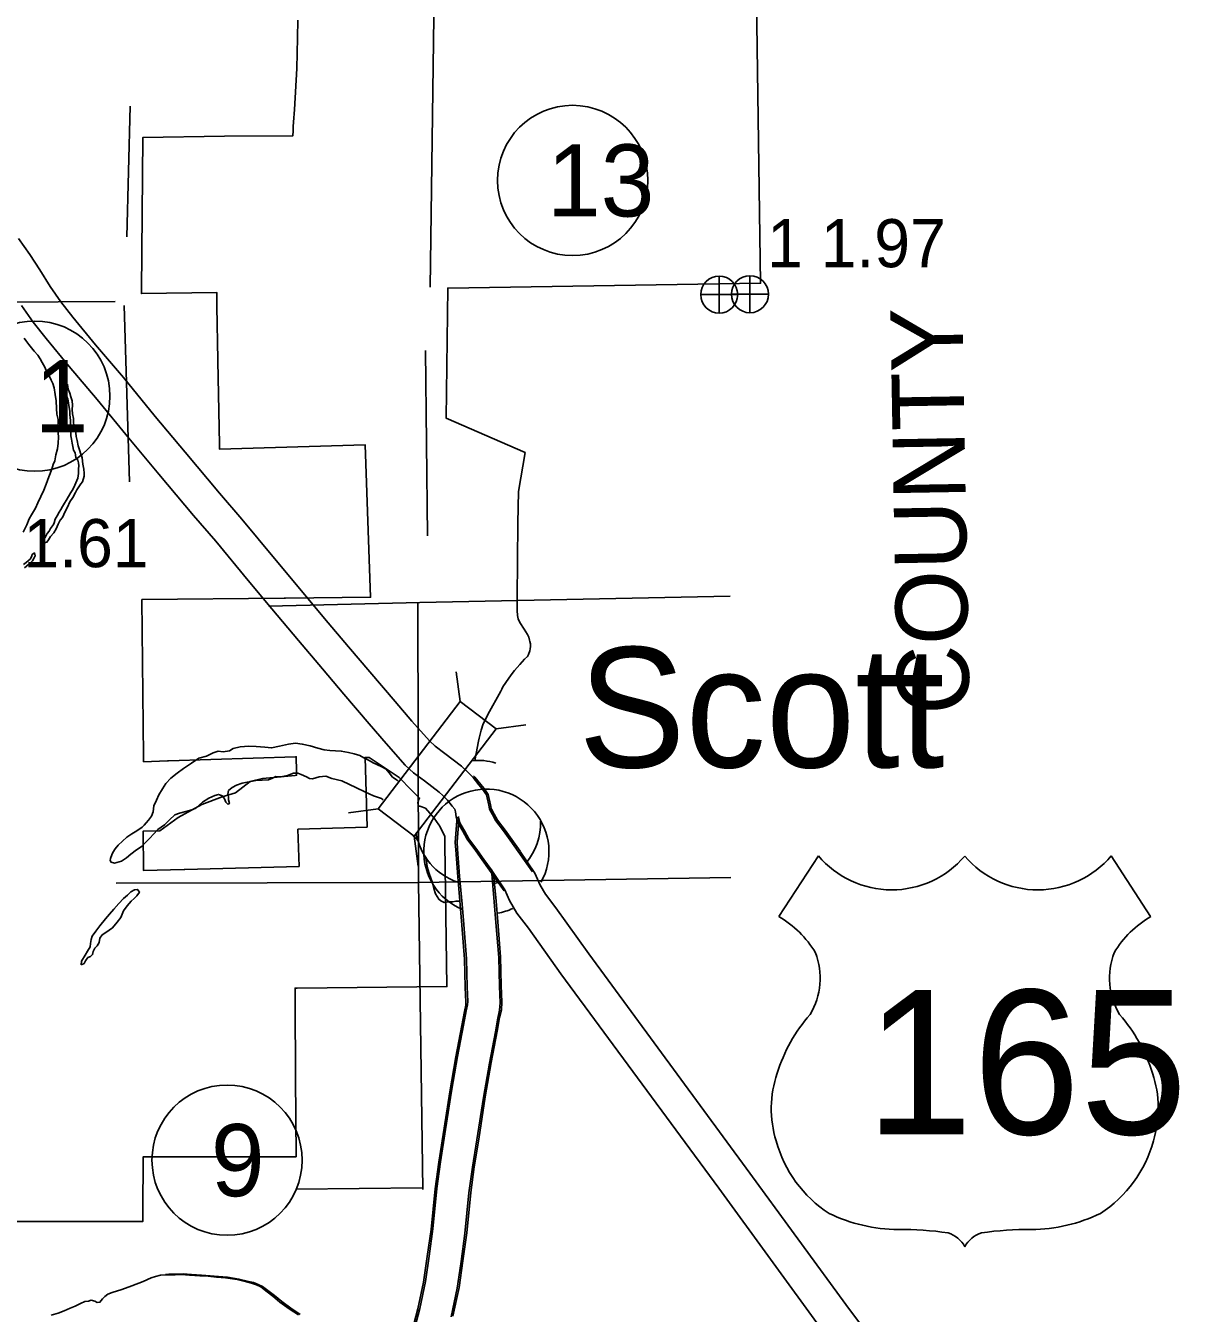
# Model space of a CAD drawing. Extents: x 1127717 to 1741049, y 2026793 to 2244711.
# Drawn here: x 1244517 to 1249585, y 2127719 to 2133375 of the extents above; entities that cross this region are included whole.
import ezdxf

# ---------------------------------------------------------------- set-up
doc = ezdxf.new("R2010")
doc.units = 0
for name, color, linetype in [('10', 7, 'Continuous'), ('15', 7, 'Continuous'), ('2', 7, 'Continuous'), ('20', 7, 'Continuous'), ('22', 7, 'Continuous'), ('24', 7, 'Continuous'), ('25', 7, 'Continuous'), ('26', 7, 'Continuous'), ('27', 7, 'Continuous'), ('30', 7, 'Continuous'), ('4', 7, 'Continuous'), ('5', 7, 'Continuous'), ('58', 7, 'Continuous'), ('6', 7, 'Continuous'), ('9', 7, 'Continuous')]:
    doc.layers.add(name, color=color, linetype=linetype)

msp = doc.modelspace()

# ---------------------------------------------------------------- linework, layer by layer
at = {"layer": '10'}
for points in [[(1246410.8, 2129898.7), (1246411.3, 2129882.2), (1246403.9, 2129787.4), (1246406, 2129754.8), (1246414.5, 2129636.5), (1246425.5, 2129513.7), (1246433.1, 2129423.7), (1246444.8, 2129274), (1246447.9, 2129150.7), (1246450.7, 2129085.6), (1246449.6, 2129072), (1246443.8, 2129045), (1246432.5, 2128982.8), (1246406, 2128845), (1246379.2, 2128691.6), (1246350.5, 2128504.5), (1246331, 2128382.1), (1246315.1, 2128264.8), (1246297.2, 2128087), (1246281, 2127967.5), (1246264.7, 2127856.1), (1246239.7, 2127738.1), (1246212.2, 2127631.6)], [(1246418.6, 2129901), (1246419.1, 2129884.5), (1246411.7, 2129789.7), (1246413.9, 2129757.1), (1246422.3, 2129638.8), (1246433.4, 2129515.9), (1246441, 2129426), (1246452.7, 2129276.3), (1246455.7, 2129153), (1246458.6, 2129087.9), (1246457.5, 2129074.3), (1246451.7, 2129047.3), (1246440.4, 2128985.1), (1246413.8, 2128847.3), (1246387, 2128693.9), (1246358.4, 2128506.7), (1246338.9, 2128384.4), (1246322.9, 2128267.1), (1246305.1, 2128089.3), (1246288.9, 2127969.8), (1246272.6, 2127858.4), (1246247.5, 2127740.4), (1246220, 2127633.9)], [(1246563.5, 2129654.9), (1246564, 2129648.6), (1246575, 2129526.7), (1246582.6, 2129435.8), (1246594.7, 2129281.7), (1246597.8, 2129155.8), (1246601, 2129082.9), (1246598.4, 2129050.3), (1246591, 2129015.8), (1246579.9, 2128955.2), (1246553.5, 2128817.9), (1246527.2, 2128667.4), (1246498.7, 2128481.3), (1246479.4, 2128360.2), (1246464.1, 2128247.2), (1246446.2, 2128069.4), (1246429.5, 2127946.6), (1246412.5, 2127829.6), (1246385.7, 2127703.7)], [(1246572.1, 2129648.3), (1246582.8, 2129529), (1246590.5, 2129438.1), (1246602.5, 2129284), (1246605.7, 2129158.1), (1246608.8, 2129085.2), (1246606.2, 2129052.5), (1246598.8, 2129018.1), (1246587.8, 2128957.4), (1246561.4, 2128820.2), (1246535.1, 2128669.7), (1246506.6, 2128483.6), (1246487.2, 2128362.4), (1246471.9, 2128249.5), (1246454.1, 2128071.7), (1246437.4, 2127948.8), (1246420.3, 2127831.9), (1246393.6, 2127706)]]:
    msp.add_lwpolyline(points, dxfattribs=at)
at = {"layer": '15'}
for points in [[(1244485, 2132440.8), (1244534.8, 2132370), (1244579.1, 2132302.4), (1244623.5, 2132228.8), (1244670.3, 2132162.7), (1244723.6, 2132094.4), (1244823, 2131973.7), (1244945.6, 2131829), (1245085.4, 2131658.1), (1245217, 2131501.5), (1245368.1, 2131321), (1245465.9, 2131207.5), (1245609.5, 2131034), (1245713.3, 2130910), (1245830, 2130770.8), (1245935.3, 2130646.3), (1246028.8, 2130535.9), (1246139.4, 2130405.9), (1246212.7, 2130319.6), (1246290, 2130232.8), (1246315.3, 2130209.6), (1246358.5, 2130178.4), (1246431.7, 2130122.5), (1246455.2, 2130099.7), (1246482, 2130072.1), (1246507.8, 2130040.2), (1246522.8, 2130021.1), (1246540.6, 2129995.9), (1246551.4, 2129950.4), (1246554, 2129934.3), (1246555, 2129930.9), (1246567.5, 2129909.5), (1246582.2, 2129882.4), (1246615.3, 2129838.5), (1246644.6, 2129797.3), (1246742.7, 2129657.8)], [(1244497.9, 2132146.5), (1244550, 2132073.2), (1244606.6, 2132000.5), (1244707.9, 2131877.6), (1244830.3, 2131733), (1244969.9, 2131562.4), (1245102, 2131405.1), (1245253.8, 2131223.9), (1245351.3, 2131110.7), (1245494.2, 2130938), (1245598.3, 2130813.6), (1245715.3, 2130674.2), (1245820.8, 2130549.4), (1245914.4, 2130438.8), (1246025.1, 2130308.8), (1246099.5, 2130221.1), (1246183.1, 2130127.3), (1246220.4, 2130093.2), (1246269, 2130058), (1246333.6, 2130008.7), (1246349.1, 2129993.6), (1246369.7, 2129972.5), (1246390.5, 2129946.7), (1246401.4, 2129932.9), (1246404.2, 2129920.9), (1246407.6, 2129900.2), (1246416.5, 2129870.7), (1246436.7, 2129836), (1246455.7, 2129801), (1246494.2, 2129749.9), (1246522.1, 2129710.6), (1246618, 2129574.3)], [(1246484.4, 2130080), (1246489.9, 2130074.4), (1246515.7, 2130042.4), (1246530.6, 2130023.4), (1246548.4, 2129998.2), (1246559.2, 2129952.7), (1246561.9, 2129936.5), (1246562.9, 2129933.2), (1246575.3, 2129911.8), (1246590, 2129884.7), (1246623.1, 2129840.8), (1246652.4, 2129799.5), (1246688.5, 2129748.4)], [(1246417.5, 2129895.8), (1246424.4, 2129873), (1246444.5, 2129838.3), (1246463.5, 2129803.3), (1246502.1, 2129752.2), (1246530, 2129712.9), (1246565.8, 2129662)], [(1246689.3, 2129747.1), (1246753.4, 2129652.1), (1246776.3, 2129600), (1246799.5, 2129560), (1246845.9, 2129500.5), (1246989.9, 2129297.3), (1247682.5, 2128356.4), (1248136.2, 2127734.8), (1248263.6, 2127566.8)], [(1246565, 2129663.2), (1246621.5, 2129579.4), (1246642.3, 2129532.1), (1246674.8, 2129475.9), (1246725.5, 2129410.9), (1246868.3, 2129209.5), (1247561.5, 2128267.7), (1248015.8, 2127645.2)]]:
    msp.add_lwpolyline(points, dxfattribs=at)
at = {"layer": '2'}
msp.add_lwpolyline([(1247726, 2133591.9), (1247745.1, 2132243.6), (1246370.9, 2132222.7), (1246363.4, 2131651.2), (1246710.2, 2131499.8), (1246682.1, 2131328.2), (1246678, 2131189.4), (1246676.3, 2130861.7), (1246675.2, 2130805.6), (1246676.9, 2130784.8), (1246679.7, 2130769.7), (1246687.2, 2130752.7), (1246706.9, 2130723.7), (1246720.7, 2130700.3), (1246726.9, 2130688.5), (1246730.4, 2130675.9), (1246731.7, 2130669.2), (1246733.6, 2130660.3), (1246734.1, 2130647.5), (1246733.5, 2130638.2), (1246731.4, 2130628.6), (1246725.4, 2130612.1), (1246720.5, 2130604.1), (1246708.3, 2130591.6), (1246688, 2130568.9), (1246663.6, 2130542.4), (1246649, 2130523.5), (1246626.4, 2130490.2), (1246613, 2130470.1), (1246607.9, 2130461.1), (1246603.3, 2130451.2), (1246546.9, 2130348.9), (1246525.2, 2130303.2), (1246519.2, 2130285.4), (1246516.9, 2130279.8), (1246509.1, 2130245.6), (1246506.4, 2130232.7), (1246495, 2130177.9), (1246489.6, 2130147.3)], dxfattribs=at)
at = {"layer": '20'}
for p, q in [((1246425.6, 2130406.4), (1246408, 2130537.3)), ((1246583, 2130286.3), (1246713.8, 2130303.9)), ((1246065.3, 2129934.2), (1245934.4, 2129916.6)), ((1246222.7, 2129814.1), (1246240.3, 2129683.3))]:
    msp.add_line(p, q, dxfattribs=at)
msp.add_lwpolyline([(1246222.7, 2129814.1), (1246583, 2130286.3), (1246425.6, 2130406.4), (1246065.3, 2129934.2)], close=True, dxfattribs=at)
at = {"layer": '22'}
for p, q in [((1247998.9, 2129728.8), (1247825.8, 2129461.1)), ((1249285.8, 2129728.8), (1249458.9, 2129461.1))]:
    msp.add_line(p, q, dxfattribs=at)
for centre, radius, start, end in [((1248321.2, 2129999.9), 421.2, 220.075, 319.6701), ((1248963.5, 2129999.9), 421.2, 220.3299, 319.925), ((1247599.7, 2129072.5), 449.7, 30.7809, 59.9883), ((1249685, 2129072.5), 449.7, 120.0117, 149.2191), ((1247698.6, 2129191.1), 308.3, 328.8105, 21.2108), ((1249586.1, 2129191.1), 308.3, 158.7892, 211.1895), ((1248504.7, 2128559.2), 719.2, 138.9565, 162.6913), ((1248780, 2128559.2), 719.2, 17.3087, 41.0435), ((1248267.3, 2128618.1), 475.2, 160.9576, 197.3819), ((1249017.4, 2128618.1), 475.2, 342.6181, 19.0424), ((1248344.7, 2128619.5), 549.9, 195.1074, 237.1312), ((1248940, 2128619.5), 549.9, 302.8688, 344.8926), ((1248354.9, 2128792.7), 706, 244.0771, 269.5779), ((1248929.8, 2128792.7), 706, 270.4221, 295.9229), ((1248371.2, 2126793.5), 1293.3, 81.1942, 90.9539), ((1248533, 2127953.1), 123.9, 28.0342, 72.9864), ((1248751.7, 2127953.1), 123.9, 107.0136, 151.9658), ((1248913.5, 2126793.5), 1293.3, 89.0461, 98.8058)]:
    msp.add_arc(centre, radius, start, end, dxfattribs=at)
at = {"layer": '24'}
for centre, start, end in [((1246503.4, 2129872.6), 73.3807, 95.8922), ((1246540.4, 2129746.6), 330.733, 246.9867), ((1246503.4, 2129872.6), 320.3322, 1.7396), ((1246503.4, 2129872.6), 189.0982, 251.1797), ((1246503.4, 2129872.6), 283.7891, 288.6769), ((1246540.4, 2129746.6), 280.4786, 294.8874)]:
    msp.add_arc(centre, 275, start, end, dxfattribs=at)
at = {"layer": '26'}
for p, q in [((1247563.4, 2132112.3), (1247563.4, 2132274.8)), ((1247698.6, 2132114.1), (1247698.6, 2132276.6)), ((1247482.2, 2132193.6), (1247644.7, 2132193.6)), ((1247617.4, 2132195.4), (1247779.9, 2132195.4))]:
    msp.add_line(p, q, dxfattribs=at)
for centre in [(1247563.4, 2132193.6), (1247698.6, 2132195.4)]:
    msp.add_circle(centre, 81.2, dxfattribs=at)
at = {"layer": '27'}
for centre in [(1246919.4, 2132695.3), (1244556.5, 2131747.8), (1245401.2, 2128391.4)]:
    msp.add_circle(centre, 330, dxfattribs=at)
at = {"layer": '4'}
msp.add_lwpolyline([(1245584.9, 2130825.6), (1246248.7, 2130840.5), (1247611, 2130868.6)], dxfattribs=at)
at = {"layer": '5'}
for points in [[(1246292.8, 2132227), (1246310.7, 2133522), (1246312.6, 2134233)], [(1244975.9, 2133020.9), (1244960.3, 2132447.8)], [(1243905.8, 2132158), (1244909.7, 2132163)], [(1244949.2, 2132146.2), (1244972, 2131371.1)], [(1246281.2, 2131134.6), (1246273.2, 2131948.2)], [(1246240, 2130840.3), (1246242.1, 2129613.8), (1246261.1, 2128262.7)], [(1244913.3, 2129607.7), (1246241.2, 2129611.8), (1247614, 2129633.3)], [(1245705.4, 2128263.4), (1246259.1, 2128270.2)]]:
    msp.add_lwpolyline(points, dxfattribs=at)
at = {"layer": '6'}
for points in [[(1245712.3, 2133398.7), (1245710.6, 2133323.5), (1245710.5, 2133322.4), (1245710.5, 2133321.4), (1245707.4, 2133186.9), (1245707.9, 2133186.9), (1245696.8, 2133007.4), (1245693.3, 2132952), (1245692.1, 2132932.3), (1245690.9, 2132913), (1245689.6, 2132891.1), (1245389.6, 2132890), (1245031.3, 2132884.5), (1245025, 2132212.5), (1245024.8, 2132198.3), (1245355.6, 2132203.4), (1245356.1, 2132181.1), (1245356.8, 2132141.9), (1245361.1, 2131907.3), (1245361.1, 2131904.6), (1245361.2, 2131902.4), (1245367.9, 2131535.7), (1245368.3, 2131514.5), (1246008.2, 2131533.6), (1246031.7, 2130864.2), (1245658.1, 2130860.4), (1245654.9, 2130860.4), (1245651.8, 2130860.4), (1245027, 2130854), (1245034.1, 2130166.3), (1245034.1, 2130164.6), (1245034.1, 2130163), (1245034.3, 2130141.9), (1245139.7, 2130145.3), (1245142, 2130145.4), (1245144.3, 2130145.5), (1245702.3, 2130163.7), (1245705, 2130163.8), (1245706.1, 2130100.4), (1245706.4, 2130082), (1245700.5, 2130081.4), (1245557.4, 2130067.7), (1245503, 2130054.3), (1245437.9, 2130005.3), (1245379.7, 2129987.9), (1245290.7, 2129953.9), (1245186.7, 2129896), (1245106.2, 2129838.7), (1245033.1, 2129837.3), (1245034.2, 2129663.8), (1245212.9, 2129668.5), (1245214.3, 2129668.6), (1245215.8, 2129668.6), (1245717.6, 2129681.8), (1245712.6, 2129845.4), (1246016.5, 2129854.5), (1246007.4, 2130160.3), (1246025, 2130159.9), (1246086.4, 2130118.8), (1246130.5, 2130089.4), (1246156.6, 2130071.9), (1246211.7, 2130017), (1246247.1, 2129981.7), (1246243.7, 2129976.7), (1246239.1, 2129961.7), (1246241.9, 2129947), (1246248.6, 2129946.8), (1246272.5, 2129937.6), (1246311.7, 2129894.5), (1246331.8, 2129863.9), (1246335.4, 2129858.4), (1246357.7, 2129812.8), (1246357.4, 2129779.9), (1246367, 2129154.1), (1245708.7, 2129147.4), (1245705.9, 2129147.4), (1245703.5, 2129147.4), (1245702.6, 2129147.4), (1245699.7, 2129147.3), (1245699.7, 2129141.8), (1245699.8, 2129136.7), (1245699.8, 2129124.2)], [(1245699.8, 2129124.2), (1245700.9, 2128968.7), (1245701.6, 2128873.5), (1245702.1, 2128802.7), (1245702.4, 2128755), (1245704.8, 2128406.6), (1245703.2, 2128406.6), (1245701.4, 2128406.6), (1245699.6, 2128406.6), (1245031.9, 2128406), (1245030.9, 2128164.1), (1245030.9, 2128161.7), (1245030.9, 2128159.6), (1245030.8, 2128121.3), (1244937.6, 2128121.4), (1244897.2, 2128121.4), (1244431.5, 2128122)]]:
    msp.add_lwpolyline(points, dxfattribs=at)
at = {"layer": '9'}
for points in [[(1244509.2, 2132001.9), (1244517.4, 2131992.1), (1244529.9, 2131974.4), (1244553.7, 2131945.6), (1244570.2, 2131927.5), (1244580.2, 2131911.3), (1244589.6, 2131895), (1244601.2, 2131874.8), (1244607.1, 2131861), (1244620.4, 2131833.3), (1244628.3, 2131818.5), (1244635.7, 2131802.7), (1244641.8, 2131784.4), (1244645.6, 2131754.9), (1244649.9, 2131727.5), (1244652.4, 2131694), (1244653.1, 2131669), (1244659.3, 2131645.1), (1244658, 2131604), (1244661, 2131567.1), (1244659.3, 2131541), (1244656.5, 2131515.9), (1244649.3, 2131490.6), (1244645, 2131463.9), (1244637.5, 2131447.2), (1244631.1, 2131427), (1244617.6, 2131393.5), (1244607.1, 2131360.7), (1244596.4, 2131334.8), (1244583.2, 2131306.9), (1244570, 2131279.5), (1244560.2, 2131256.2), (1244541.6, 2131225.6), (1244532.1, 2131208.3), (1244520.9, 2131182.9), (1244504.8, 2131150.4)], [(1244694.1, 2131804.4), (1244700.2, 2131799.1), (1244702.8, 2131779.1), (1244709.8, 2131761.3), (1244715.3, 2131744.4), (1244720.3, 2131726.5), (1244722.3, 2131707.6), (1244721.4, 2131689.5), (1244721.9, 2131670), (1244726.5, 2131650.1), (1244726.6, 2131628.6), (1244732.3, 2131606.2), (1244736.8, 2131586.8), (1244737.8, 2131570.8), (1244742.3, 2131552.4), (1244747, 2131529), (1244753.5, 2131511.2), (1244759, 2131492.8), (1244764.9, 2131477.4), (1244767.8, 2131449), (1244771.4, 2131427.6), (1244772.9, 2131409.1), (1244772.8, 2131395.5), (1244766.5, 2131371.8), (1244758.8, 2131362.1), (1244741.6, 2131335.5), (1244735.4, 2131323.8), (1244723.6, 2131302), (1244711.1, 2131283.6), (1244699.9, 2131259.7), (1244690.4, 2131240.4), (1244678.7, 2131215), (1244668.6, 2131202.7), (1244659.6, 2131185.4), (1244650.2, 2131164.1), (1244640.7, 2131147.3), (1244626.2, 2131130.9), (1244616.6, 2131116.6), (1244609.9, 2131106.4), (1244599.6, 2131103.1), (1244592.6, 2131103.4), (1244592.7, 2131114.4), (1244601.4, 2131126.7), (1244610.9, 2131144), (1244619, 2131155.2), (1244626.2, 2131165.9), (1244638.2, 2131183.3), (1244641.4, 2131191.9), (1244646.5, 2131207.1), (1244654.5, 2131221.8), (1244663.5, 2131238.6), (1244670.2, 2131249.8), (1244678.3, 2131263.6), (1244686.4, 2131277.9), (1244695, 2131289.6), (1244704.5, 2131306.4), (1244715, 2131323.8), (1244723.1, 2131338), (1244732.5, 2131356.3), (1244737.2, 2131367), (1244745.1, 2131387.2), (1244748, 2131408.3), (1244747.9, 2131428.4), (1244750, 2131441), (1244749.1, 2131455), (1244745.8, 2131466.4), (1244737.5, 2131477.6), (1244733.9, 2131499.1), (1244727, 2131510.9), (1244724.1, 2131526.3), (1244721.2, 2131541.3), (1244717.2, 2131559.2), (1244715.3, 2131573.2), (1244715.3, 2131589.2), (1244715.8, 2131606.7), (1244714, 2131617.7), (1244713.1, 2131630.7), (1244713.3, 2131640.2), (1244711, 2131667.2), (1244710.1, 2131681.7), (1244705.9, 2131707.1), (1244704.1, 2131718.6), (1244701.6, 2131734.5), (1244696.2, 2131748.9), (1244692.9, 2131760.3), (1244691, 2131773.8), (1244690.2, 2131785.3), (1244689.7, 2131800.8)], [(1244689.7, 2131800.8), (1244694.1, 2131804.4)], [(1244507, 2131008.2), (1244519.2, 2131016.6), (1244528.4, 2131025.4), (1244535.7, 2131032.1), (1244541.4, 2131041.8), (1244545.6, 2131051.9), (1244554.9, 2131058.7), (1244557.8, 2131046.8), (1244554, 2131037.6), (1244545.9, 2131024.9), (1244530.9, 2131009.4), (1244511.4, 2130992.8)], [(1245027.5, 2129854), (1245037.7, 2129863.3), (1245046, 2129872.6), (1245056.1, 2129884.4), (1245069.1, 2129902.3), (1245076, 2129921.5), (1245079.2, 2129948.2), (1245091, 2129973), (1245101.8, 2129995.9), (1245117.5, 2130022.4), (1245132.8, 2130045.4), (1245153.6, 2130069), (1245182.4, 2130090.9), (1245209.7, 2130112.7), (1245244.5, 2130135.7), (1245276.8, 2130156.7), (1245311.5, 2130165.7), (1245339.5, 2130181.1), (1245362.8, 2130187.8), (1245383.8, 2130185.9), (1245411.7, 2130189.2), (1245427.4, 2130199.6), (1245459.1, 2130207.1), (1245497.4, 2130210.2), (1245528.4, 2130208.6), (1245567.5, 2130205.7), (1245596.5, 2130202.5), (1245632.2, 2130210.1)], [(1245632.2, 2130210.1), (1245670.4, 2130218.7), (1245702.2, 2130223.1), (1245731.3, 2130219.5), (1245766.4, 2130212), (1245800.2, 2130200.9), (1245827.9, 2130194.2), (1245853.4, 2130191), (1245877.9, 2130190.2), (1245902.9, 2130188.4), (1245934, 2130182.3), (1245959.6, 2130177), (1245984.8, 2130169.7), (1246002.6, 2130158.7), (1246025.9, 2130146.4), (1246043.6, 2130137.4), (1246078.6, 2130120.4), (1246099.9, 2130108.5), (1246113.8, 2130093.4), (1246128.3, 2130073.8), (1246148.2, 2130060.3), (1246152.8, 2130056.6)], [(1246087.3, 2129974.1), (1246079.2, 2129979.7), (1246044.9, 2129991.2), (1246006.4, 2130009.1), (1245969.5, 2130027.1), (1245905.7, 2130057.3), (1245860.9, 2130068.5), (1245835.2, 2130077.8), (1245805.3, 2130075.9), (1245776.1, 2130066.5), (1245763.6, 2130068.2), (1245749.9, 2130075.8), (1245727.2, 2130086.1), (1245712, 2130091.2), (1245693.1, 2130091.2), (1245666.9, 2130081.9), (1245637.6, 2130075), (1245615.1, 2130076.9), (1245600.9, 2130069), (1245583.1, 2130061.9), (1245555.2, 2130060.1), (1245528.3, 2130059.3), (1245467.7, 2130047.6), (1245442, 2130039.3), (1245423.3, 2130028.3), (1245407.2, 2130014.8), (1245404.2, 2129998.7), (1245407, 2129987.7), (1245406.9, 2129974.2), (1245411.9, 2129957.8), (1245404.5, 2129954.6), (1245395.8, 2129963.4), (1245389.3, 2129978.7), (1245380.5, 2129991.5), (1245364.3, 2129998), (1245347, 2129993), (1245321.3, 2129981.7), (1245292.9, 2129963.9), (1245278.8, 2129951.4), (1245263.7, 2129938), (1245246.4, 2129931), (1245219.7, 2129923.2), (1245192.5, 2129915.9), (1245172.2, 2129907.8), (1245148.9, 2129886.1), (1245126.1, 2129863.9), (1245097.7, 2129844.5), (1245078.3, 2129823.4), (1245061.4, 2129806.4), (1245042, 2129785.8), (1245028.4, 2129771.4), (1245003.9, 2129754.7), (1244978, 2129735.4), (1244960, 2129719.8), (1244937, 2129705.2), (1244907.3, 2129696.8), (1244892.2, 2129700.3), (1244888, 2129708.2), (1244889.7, 2129717.3), (1244895.3, 2129732), (1244899.9, 2129743.6), (1244909, 2129758.9), (1244923, 2129774.9), (1244941.4, 2129792.9), (1244960.4, 2129810), (1244983.4, 2129825.2), (1245004.5, 2129838.8), (1245027.5, 2129854)], [(1246219.2, 2129815.2), (1246228.9, 2129808.8), (1246238.5, 2129796.5)], [(1246273.1, 2129721.7), (1246277.3, 2129706), (1246279.2, 2129690), (1246283.3, 2129669.6), (1246289.9, 2129646.8), (1246301.9, 2129613.6), (1246310.2, 2129584.8), (1246317.4, 2129561.9), (1246324.2, 2129550.1), (1246331.5, 2129537.3), (1246340.2, 2129530), (1246354.9, 2129523), (1246375.3, 2129525.6), (1246393.3, 2129526.6), (1246406.2, 2129529), (1246422.1, 2129528.9), (1246423.2, 2129528.4)], [(1244760, 2129249.3), (1244761, 2129265.9), (1244778.2, 2129291.4), (1244788.7, 2129310.2), (1244800.1, 2129328.1), (1244801.7, 2129343.7), (1244803.7, 2129360.8), (1244809.2, 2129375.9), (1244824.6, 2129397.4), (1244842.4, 2129421.5), (1244867, 2129451.2), (1244885.3, 2129472.3), (1244904.2, 2129493.9), (1244925.9, 2129518.5), (1244946.3, 2129540.2), (1244963.3, 2129556.2), (1244978.8, 2129570.2), (1244994, 2129579.6), (1245008, 2129580.5), (1245016.3, 2129568.7), (1245004.3, 2129552.4), (1244992.6, 2129541.5), (1244979.5, 2129529.1), (1244961.7, 2129508.1), (1244946.8, 2129486.6), (1244934.7, 2129457.2), (1244917.8, 2129436.7), (1244898, 2129412.6), (1244869.2, 2129391.2), (1244853, 2129380.7), (1244842.5, 2129366.4), (1244839.5, 2129347.8), (1244830.9, 2129333.5), (1244820.8, 2129322.7), (1244812.7, 2129308.4), (1244810.1, 2129294.8), (1244800.9, 2129285.6), (1244790, 2129281.2), (1244779.9, 2129266.9), (1244773.3, 2129255.2)], [(1244760, 2129249.3), (1244773.3, 2129255.2)], [(1244628.7, 2127711.1), (1244659.5, 2127719.5), (1244685.1, 2127728.8), (1244711.7, 2127741.5), (1244733.9, 2127750.7), (1244758, 2127762.4), (1244776.8, 2127770), (1244792.2, 2127772.4), (1244804.1, 2127776.8), (1244819.6, 2127772.7), (1244830.8, 2127766), (1244842.3, 2127767.4), (1244853.3, 2127781.7), (1244864, 2127792.5), (1244877.7, 2127803), (1244896.4, 2127810.5), (1244939, 2127823.3), (1244983.4, 2127839.6), (1245033.3, 2127858.6), (1245068.3, 2127875.1), (1245086.1, 2127880.1), (1245109.4, 2127886.8), (1245138.3, 2127888.1), (1245173.2, 2127888.2), (1245201.1, 2127889.5), (1245236.7, 2127886.5), (1245281.7, 2127883.3), (1245318.7, 2127881.4), (1245355.2, 2127877.9), (1245394.7, 2127874.6), (1245445.4, 2127867), (1245487.1, 2127856.7), (1245509.2, 2127851.3), (1245530.4, 2127843.4), (1245549.2, 2127834.5), (1245577.8, 2127812.3), (1245601.7, 2127793.9), (1245633.4, 2127767.8), (1245674.2, 2127738.9), (1245714.4, 2127711.6)], [(1245130.4, 2127889.7), (1245146.1, 2127890.4), (1245181.1, 2127890.4), (1245209, 2127891.8), (1245244.5, 2127888.8), (1245289.5, 2127885.6), (1245326.5, 2127883.6), (1245363.1, 2127880.2), (1245402.6, 2127876.8), (1245453.2, 2127869.3), (1245495, 2127859), (1245517.1, 2127853.6), (1245538.3, 2127845.7), (1245557, 2127836.8), (1245585.6, 2127814.5), (1245609.6, 2127796.2), (1245641.3, 2127770.1), (1245682.1, 2127741.2), (1245722.3, 2127713.8)]]:
    msp.add_lwpolyline(points, dxfattribs=at)

# ---------------------------------------------------------------- texts
at = {"layer": '22'}
msp.add_text('165', height=633.6, dxfattribs=at).set_placement((1248206.5, 2128505.2))
at = {"layer": '24'}
msp.add_text('Scott', height=528, dxfattribs=at).set_placement((1246944.6, 2130116.7))
at = {"layer": '25'}
msp.add_text('1 1.97', height=211.2, dxfattribs=at).set_placement((1247773.6, 2132314))
at = {"layer": '27'}
for s, p in [('13', (1246807.2, 2132536.9)), ('1', (1244556.5, 2131589.4)), ('9', (1245330.4, 2128233))]:
    msp.add_text(s, height=316.8, dxfattribs=at).set_placement(p)
at = {"layer": '30'}
msp.add_text('COUNTY', height=316.8, rotation=91, dxfattribs=at).set_placement((1248662.9, 2130351.2))
at = {"layer": '58'}
msp.add_text('1.61', height=211.2, dxfattribs=at).set_placement((1244506.7, 2130996.4))

doc.saveas('drawing.dxf')
